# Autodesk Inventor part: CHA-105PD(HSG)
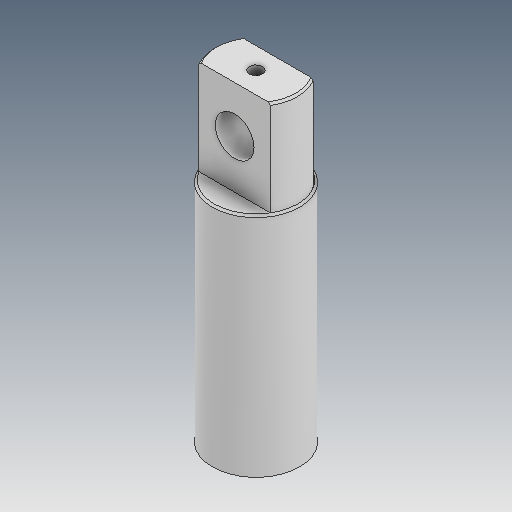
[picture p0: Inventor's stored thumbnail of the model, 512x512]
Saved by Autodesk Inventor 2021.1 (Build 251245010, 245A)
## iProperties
Created: 2021-05
Part Number: CHA-105PD(HSG)
Material: Ogólny
Document SubType Name: Modeling
Designer: user
Density: 1 g/cm^3
Appearance: Domyślna
Author: user
Revision Number: ÈÎºÎ
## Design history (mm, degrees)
feature "M8 ÂÝÎÆ¿×1"
node "Bryła1"
